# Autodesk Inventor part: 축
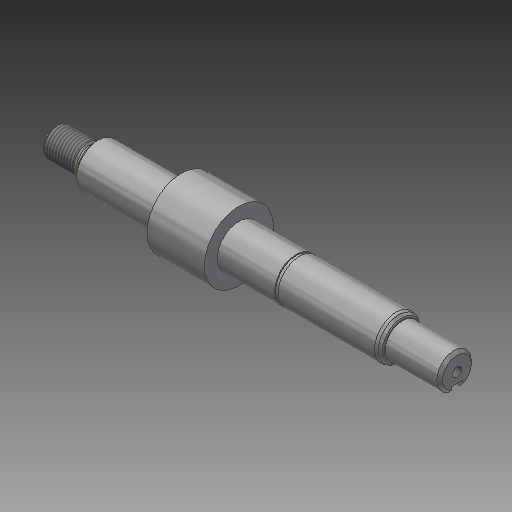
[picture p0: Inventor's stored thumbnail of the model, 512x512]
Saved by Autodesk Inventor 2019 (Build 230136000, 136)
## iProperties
Created: 2016-08
Part Number: 축
Material: 강철, 탄소
Document SubType Name: Modeling
Designer: mduedu
Density: 7.87 g/cm^3
Appearance: 강철
Author: mduedu
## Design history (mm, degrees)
sketch "스케치1"
  geometry: L1 (-70, 0)-(70, 0); L2 (-70, 0)-(-70, 5); L3 (-70, 5)-(-56, 5); L4 (-56, 5)-(-56, 7.5); L5 (-56, 7.5)-(49.355, 7.5); L6 (51, 7.5)-(51, 6.55); L7 (51, 6)-(70, 6); L8 (70, 6)-(70, 0); L9 (51, 6.55)-(49.355, 7.5); L10 (49.355, 7.5)-(51, 7.5); L11 (51, 6.55)-(51, 6); 2 further points
  constraints: 22 end point, 7 parallel, 2 perpendicular, 1 coincident, 1 horizontal, 1 midpoint
  dimensions: "d0" = 140 distance of L1.start L1.end; "d2" = 14 distance of L2.end L3.end; "d3" = 19 distance of L7.start L7.end; "d4" = 10 diameter of L3 L1; "d5" = 15 diameter of L5 L1; "d6" = 12 diameter of L7 L1; "d63" = 13.1 diameter of L6.end L1; "d64" = 30 deg angle of L5 L9
revolve "회전1" sketch "스케치1" stored, may be unused: angle "d7" = 90 deg
sketch "스케치2"
  geometry: L1 (-56, -5)-(-56, 5) reference; L2 (70, -6)-(70, 6) reference; L3 (-56, 0)-(70, 0); L4 (-58, 4.5)-(-58, 5); L5 (-58, 5)-(-56, 5); L6 (-56, 5)-(-56, 4.5); L7 (-58, 4.5)-(-56, 4.5); 1 further point
  constraints: 10 end point, 2 midpoint, 1 parallel, 1 perpendicular, 1 point on line
  dimensions: "d8" = 2 distance of L4.end L5.end; "d10" = 10 diameter of L5 L3; "d11" = 9 diameter of L7 L3
revolve "회전2" sketch "스케치2" stored, may be unused: angle "d12" = 90 deg
node "작업 평면1"
sketch "스케치3"
  geometry: C1 r 12 at (0, 0); 1 further point
  constraints: 1 centre point, 1 coincident
  dimensions: "d15" = 24 diameter of C1
extrude "돌출1" join sketch "스케치3" distance "d16" = 20; taper "d17" = 0 deg
sketch "스케치5"
  geometry: L1 (-70, -5)-(-70, 5) reference; L2 (70, -6)-(70, 6) reference; L3 (-70, 0)-(70, 0); L4 (-6, 7.5)-(49.355, 7.5) reference; L5 (15.15, 7.5)-(14, 7.5); L6 (14, 7.5)-(14, 7.15); L7 (14, 7.15)-(15.15, 7.15); L8 (15.15, 7.15)-(15.15, 7.5); 1 further point
  constraints: 10 end point, 2 midpoint, 2 parallel, 1 horizontal, 1 perpendicular, 1 point on line
  dimensions: "d19" = 56 distance between parallel lines of L6 L2; "d20" = 1.15 distance between parallel lines of L8 L6; "d21" = 14.3 diameter of L7 L3
revolve "회전3" sketch "스케치5" stored, may be unused: angle "d22" = 90 deg
node "작업 평면3"
sketch "스케치6"
  geometry: L1 (6.5, 2)-(-9.5, 2); L2 (-9.5, 2)-(-9.5, -2); L3 (-9.5, -2)-(6.5, -2); L4 (-9.5, 6)-(-9.5, -6) reference; A1 r 2 centre (6.5, 0) between (6.5, -2) and (6.5, 2); 2 further points
  constraints: 6 end point, 2 midpoint, 2 point on circle, 2 tangent, 1 centre point, 1 horizontal, 1 horizontal alignment, 1 parallel, 1 perpendicular
  dimensions: "d23" = 4 distance between parallel lines of L3 L1; "d62" = 18 dimension on A1 L2
extrude "돌출2" cut sketch "스케치6" distance "d25" = 2.5; taper "d26" = 0 deg
feature "스레드1" dims "d27" = 10, "d28" = 0
fillet "모깎기1" dims "d65" = 2
fillet "모깎기2" dims "d66" = 0.5
chamfer "모따기5" distance "d41" = 0.5; stored, may be unused: second distance "d42" = 2, angle "d43" = 45 deg
chamfer "모따기7" distance "d47" = 1; stored, may be unused: second distance "d48" = 2, angle "d49" = 45 deg
chamfer "모따기8" distance "d50" = 1; stored, may be unused: second distance "d51" = 2, angle "d52" = 45 deg
sketch "스케치8"
  geometry: 1 further point
hole "구멍1" sketch "스케치8" at (2, 3.5) diameter "d53" = 3.242; stored, may be unused: countersink angle "d57" = 90 deg, drill point angle "d59" = 120 deg; dims "d54" = 10, "d55" = 4, "d56" = 2, "d58" = 12
node "솔리드1"
other parameters: "d13" = -44
